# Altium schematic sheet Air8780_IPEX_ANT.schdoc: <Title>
size 419 x 266 mm; Name: SIZEB; Symbol: SIZEB; Device: SIZEB; Drawn By: <Drawn By>; Checked By: <Checked By>; QC By: <QC By>; Released By: <Released By>; Drawn Date: <Drawn Date>; Checked Date: <Checked Date>; QC Date: <QC Date>; Release Date: <Release Date>; Company Name: <Company Name>; Code: <Code>; Sheet Size: B; Drawing Number: <Drawing Number>; Revision: <Revision>; Scale: <Scale>; Sheet Number: 1; Number of Sheets: 1
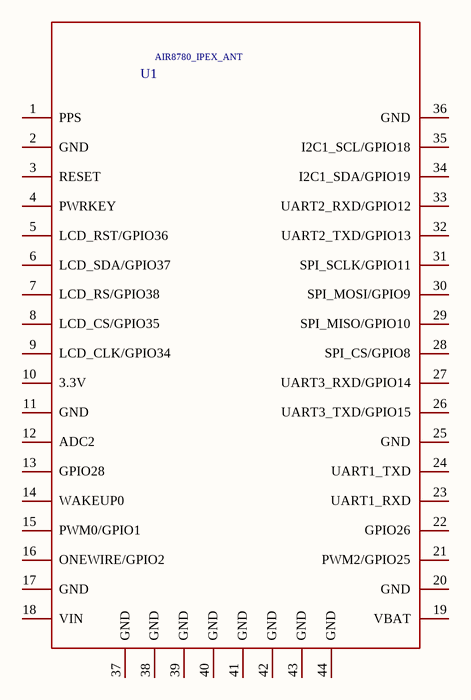
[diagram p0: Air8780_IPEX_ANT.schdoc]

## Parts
U1  AIR8780_IPEX_ANT

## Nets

Not connected (* = marked no-connect by the designer): U1 1(PPS) 2(GND) 3(RESET) 4(PWRKEY) 5(LCD_RST/GPIO36) 6(LCD_SDA/GPIO37) 7(LCD_RS/GPIO38) 8(LCD_CS/GPIO35) 9(LCD_CLK/GPIO34) 10(3.3V) 11(GND) 12(ADC2) 13(GPIO28) 14(WAKEUP0) 15(PWM0/GPIO1) 16(ONEWIRE/GPIO2) 17(GND) 18(VIN) 19(VBAT) 20(GND) 21(PWM2/GPIO25) 22(GPIO26) 23(UART1_RXD) 24(UART1_TXD) 25(GND) 26(UART3_TXD/GPIO15) 27(UART3_RXD/GPIO14) 28(SPI_CS/GPIO8) 29(SPI_MISO/GPIO10) 30(SPI_MOSI/GPIO9) 31(SPI_SCLK/GPIO11) 32(UART2_TXD/GPIO13) 33(UART2_RXD/GPIO12) 34(I2C1_SDA/GPIO19) 35(I2C1_SCL/GPIO18) 36(GND) 37(GND) 38(GND) 39(GND) 40(GND) 41(GND) 42(GND) 43(GND) 44(GND)

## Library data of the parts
U1 = AIR8780_IPEX_ANT: Add into BOM: yes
